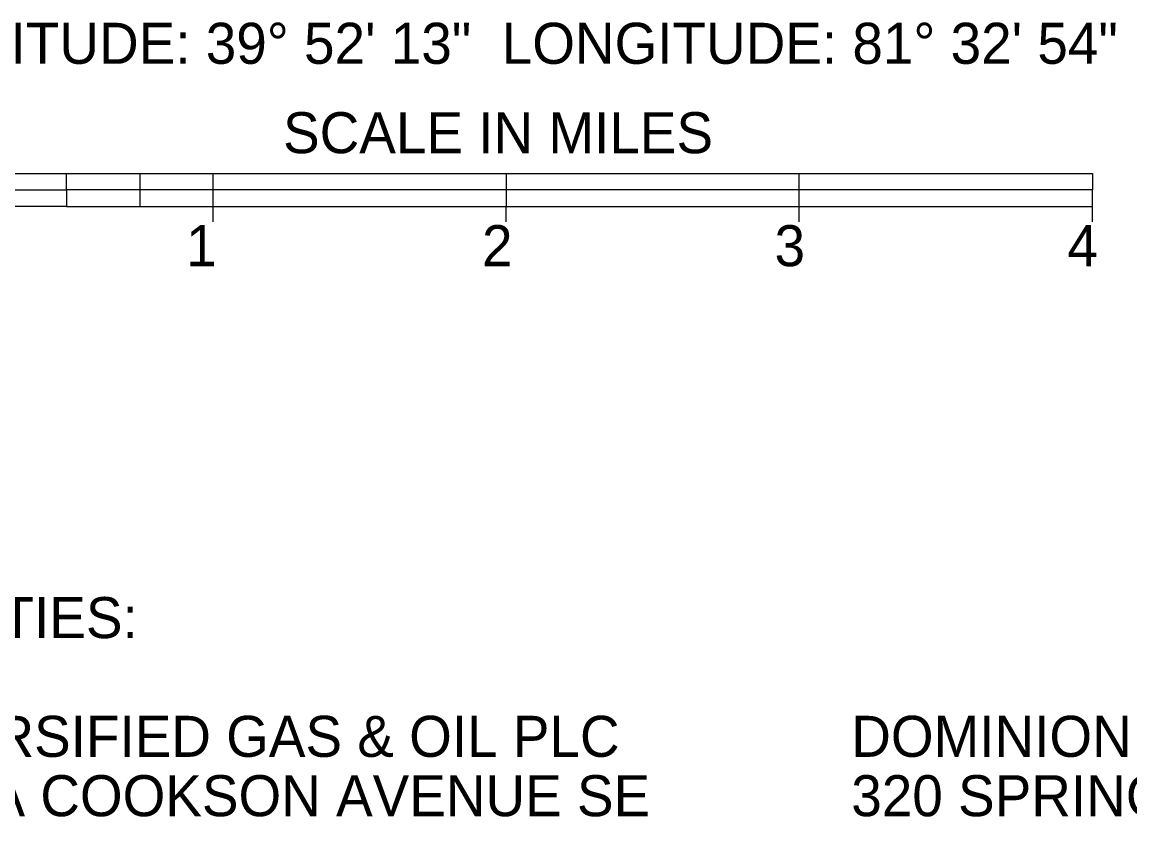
# Model space of a CAD drawing. Extents: x 0 to 34, y 0 to 22.
# Drawn here: x 2.435 to 6.214, y 11.051 to 13.786 of the extents above; entities that cross this region are included whole.
import ezdxf

# ---------------------------------------------------------------- set-up
doc = ezdxf.new("R2010")
doc.units = 0
doc.layers.add('SH_Data', color=7, linetype='Continuous')
doc.layers.add('SH_Text', color=7, linetype='Continuous')

msp = doc.modelspace()

# ---------------------------------------------------------------- linework, layer by layer
at = {"layer": 'SH_Data'}
for p, q in [((2.3359, 13.27), (2.5859, 13.27)), ((2.5859, 13.2138), (2.5859, 13.27)), ((2.5859, 13.27), (2.8359, 13.27)), ((2.8359, 13.27), (3.0859, 13.27)), ((2.8359, 13.27), (2.8359, 13.2138)), ((3.0859, 13.2138), (3.0859, 13.27)), ((3.0859, 13.27), (4.0859, 13.27)), ((4.0859, 13.27), (5.0859, 13.27)), ((4.0859, 13.27), (4.0859, 13.2138)), ((5.0859, 13.2138), (5.0859, 13.27)), ((5.0859, 13.27), (6.0859, 13.27)), ((6.0859, 13.27), (6.0859, 13.2138)), ((2.3359, 13.2138), (2.5859, 13.2138)), ((2.5859, 13.2138), (2.5859, 13.1575)), ((2.8359, 13.2138), (2.5859, 13.2138)), ((3.0859, 13.2138), (2.8359, 13.2138)), ((2.8359, 13.2138), (2.8359, 13.1575)), ((3.0859, 13.1575), (3.0859, 13.2138)), ((4.0859, 13.2138), (3.0859, 13.2138)), ((5.0859, 13.2138), (4.0859, 13.2138)), ((4.0859, 13.2138), (4.0859, 13.1575)), ((5.0859, 13.1575), (5.0859, 13.2138)), ((6.0859, 13.2138), (5.0859, 13.2138)), ((6.0859, 13.1575), (6.0859, 13.2138)), ((2.5859, 13.1575), (2.3359, 13.1575)), ((2.5859, 13.1575), (2.8359, 13.1575)), ((2.8359, 13.1575), (3.0859, 13.1575)), ((3.0859, 13.1575), (4.0859, 13.1575)), ((3.0859, 13.1045), (3.0859, 13.1575)), ((4.0859, 13.1575), (5.0859, 13.1575)), ((4.0859, 13.1045), (4.0859, 13.1575)), ((5.0859, 13.1575), (6.0859, 13.1575)), ((5.0859, 13.1045), (5.0859, 13.1575)), ((6.0859, 13.1045), (6.0859, 13.1575))]:
    msp.add_line(p, q, dxfattribs=at)

# ---------------------------------------------------------------- texts
for s, p in [('LATITUDE: 39° 52\' 13"  LONGITUDE: 81° 32\' 54"', (2.0519, 13.6437)), ('SCALE IN MILES', (3.3246, 13.3387)), ('1', (2.9937, 12.9534)), ('2', (4.0034, 12.9534)), ('3', (5.0014, 12.9534)), ('4', (6.0003, 12.9534))]:
    msp.add_text(s, height=0.14, dxfattribs=at).set_placement(p)
at = {"layer": 'SH_Text'}
for s, p in [('UTILITIES:', (1.9031, 11.6848)), ('DIVERSIFIED GAS & OIL PLC', (1.9031, 11.2798)), ('DOMINION', (5.2631, 11.2798)), ('1026A COOKSON AVENUE SE', (1.9031, 11.0773)), ('320 SPRINGSIDE DRIVE SUITE, 320', (5.2631, 11.0773))]:
    msp.add_text(s, height=0.14, dxfattribs=at).set_placement(p)

doc.saveas('drawing.dxf')
